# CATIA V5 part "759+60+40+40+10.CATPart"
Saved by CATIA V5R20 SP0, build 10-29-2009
Part number: 759+60+40+40+10
Revision: TUTTO
Definition: NON CONOSCIUTO
Nomenclature: 759+60+40+40+10
Source: Unknown
Bounding box of the stored display mesh (mm): x -30 to 30, y -20 to 20, z 0 to 40
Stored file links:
  C:\Users\Utente\Desktop\IO LAVORO\3D X SITO CF\X 3D SITO CF 27-09-2020\759\759+60+40+40+10.CATPart
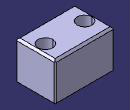
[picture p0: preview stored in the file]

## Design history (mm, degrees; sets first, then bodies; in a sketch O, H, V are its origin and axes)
Body1 "Smusso4" (main body)
  Solid1: solid without history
